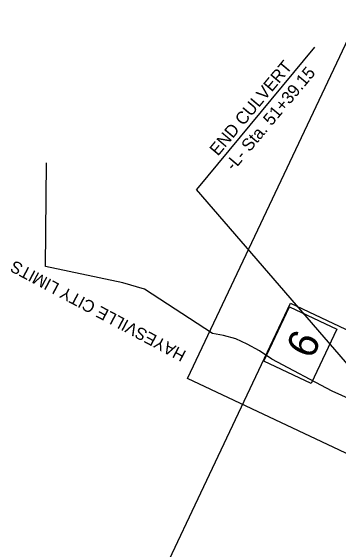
# Model space of a CAD drawing. Extents: x 555292 to 2368606, y 503623 to 1171444.
# Drawn here: x 2359960 to 2361051, y 1164815 to 1166609 of the extents above; entities that cross this region are included whole.
import ezdxf

# ---------------------------------------------------------------- set-up
doc = ezdxf.new("R2010")
doc.units = 0
for name, color, linetype in [('Default', 7, 'Continuous'), ('Old_Level_48', 7, 'Continuous'), ('Prop Horizontal Alignment Station Label', 7, 'Continuous'), ('Sheet Title CELL', 7, 'Continuous')]:
    doc.layers.add(name, color=color, linetype=linetype)

msp = doc.modelspace()

# ---------------------------------------------------------------- linework, layer by layer
at = {"layer": 'Old_Level_48'}
msp.add_lwpolyline([(2361694.7, 1165519.7), (2361657.5, 1165522.1), (2361579.9, 1165525.5), (2361500.9, 1165527.2), (2361409.7, 1165494.3), (2361393.5, 1165484.8), (2361352.7, 1165454.5), (2361302.7, 1165408.9), (2361242.7, 1165350.5), (2361149.7, 1165288.3), (2361031, 1165341.5), (2360829.6, 1165448.4), (2360789.2, 1165475.8), (2360747.2, 1165498.6), (2360709.9, 1165516.4), (2360669.1, 1165527.3), (2360632.5, 1165533.3), (2360405, 1165681.4), (2360333.3, 1165702.6), (2360076, 1165757.3), (2360078.4, 1166102.1)], dxfattribs=at)
at = {"layer": 'Prop Horizontal Alignment Station Label'}
for p in [(2360972.1, 1166488.1), (2361194.1, 1165301.2)]:
    msp.add_line(p, (2360578.7, 1166013.6), dxfattribs=at)
at = {"layer": 'Sheet Title CELL'}
for points in [[(2362215, 1166440), (2361502.8, 1164933.3), (2360548.9, 1165384.2), (2361261.1, 1166890.9)], [(2361846.2, 1165184.1), (2361134.1, 1163677.4), (2360180.2, 1164128.3), (2360892.3, 1165635)], [(2360803.8, 1165441.7), (2360889.3, 1165622.6), (2361046.2, 1165548.4), (2360960.7, 1165367.6)]]:
    msp.add_lwpolyline(points, close=True, dxfattribs=at)

# ---------------------------------------------------------------- texts
at = {"layer": 'Default'}
msp.add_text('6', height=100, rotation=64.7037, dxfattribs=at).set_placement((2360963.9, 1165444.6))
at = {"layer": 'Prop Horizontal Alignment Station Label'}
for s, height, rotation, p in [('END CULVERT', 41.248, 49.9796, (2360650.2, 1166123.2)), ('-L- Sta. 51+39.15', 41.248, 49.9796, (2360702.6, 1166073.5)), ('HAYESVILLE CITY LIMITS', 40, 152.0341, (2360547.7, 1165473.6))]:
    msp.add_text(s, height=height, rotation=rotation, dxfattribs=at).set_placement(p)

doc.saveas('drawing.dxf')
